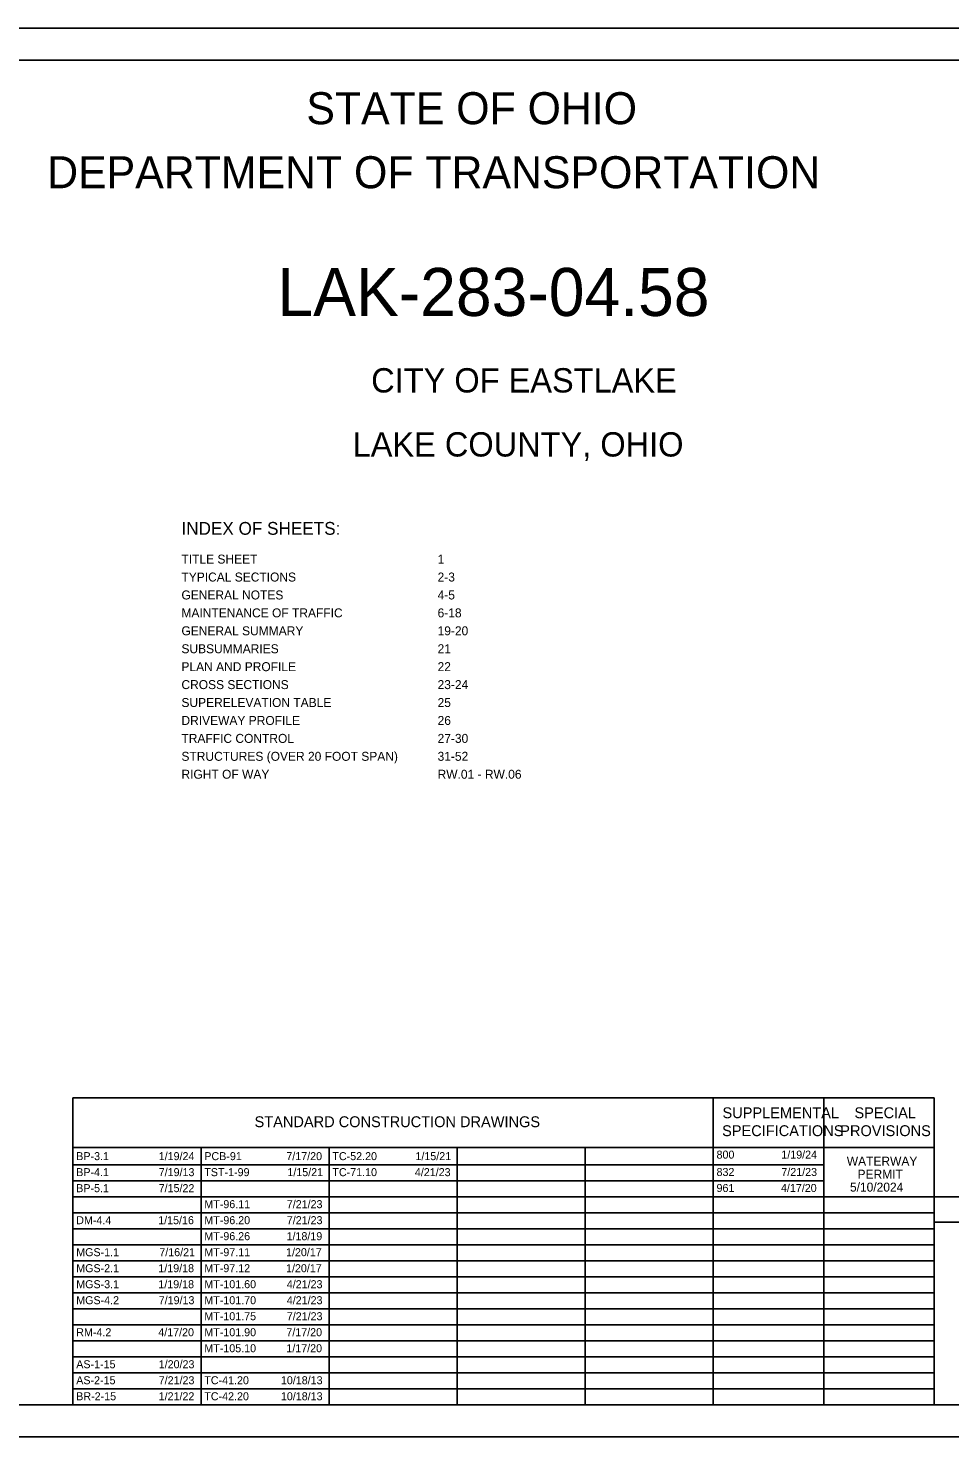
# Model space of a CAD drawing. Extents: x -5.4 to 71.3, y -12 to 22.
# Drawn here: x 9.45 to 23.84, y 0 to 22 of the extents above; entities that cross this region are included whole.
import ezdxf

# ---------------------------------------------------------------- set-up
doc = ezdxf.new("R2010")
doc.units = 0
for name, color, linetype in [('SH_Border', 7, 'Continuous'), ('SH_Cut_Line', 7, 'Continuous'), ('SH_Data', 7, 'Continuous'), ('SH_Text', 7, 'Continuous')]:
    doc.layers.add(name, color=color, linetype=linetype)

msp = doc.modelspace()

# ---------------------------------------------------------------- linework, layer by layer
at = {"layer": 'SH_Border'}
msp.add_lwpolyline([(1.5, 21.5), (33.5, 21.5), (33.5, 0.5), (1.5, 0.5)], close=True, dxfattribs=at)
at = {"layer": 'SH_Cut_Line'}
msp.add_lwpolyline([(0, 0), (34, 0), (34, 22), (0, 22)], close=True, dxfattribs=at)
at = {"layer": 'SH_Data'}
for p, q in [((10.15, 5.292), (23.6, 5.292)), ((10.15, 0.5), (10.15, 5.292)), ((20.15, 0.5), (20.15, 5.292)), ((21.875, 0.5), (21.875, 5.292)), ((23.6, 0.5), (23.6, 5.292)), ((10.15, 4.521), (23.6, 4.521)), ((12.15, 0.5), (12.15, 4.521)), ((14.15, 0.5), (14.15, 4.521)), ((16.15, 0.5), (16.15, 4.521)), ((18.15, 0.5), (18.15, 4.521)), ((10.15, 4.25), (21.875, 4.25)), ((10.15, 4), (21.875, 4)), ((10.15, 3.75), (23.6, 3.75)), ((23.6, 0.5), (23.6, 3.75)), ((23.6, 0.5), (23.6, 3.75)), ((23.6, 3.75), (26.4, 3.75)), ((10.15, 3.5), (23.6, 3.5)), ((23.6, 3.35), (26.4, 3.35)), ((10.15, 3.25), (23.6, 3.25)), ((10.15, 3), (23.6, 3)), ((10.15, 2.75), (23.6, 2.75)), ((10.15, 2.5), (23.6, 2.5)), ((10.15, 2.25), (23.6, 2.25)), ((10.15, 2), (23.6, 2)), ((10.15, 1.75), (23.6, 1.75)), ((10.15, 1.5), (23.6, 1.5)), ((10.15, 1.25), (23.6, 1.25)), ((10.15, 1), (23.6, 1)), ((10.15, 0.75), (23.6, 0.75)), ((23.6, 0.5), (26.4, 0.5)), ((23.6, 0.5), (26.4, 0.5))]:
    msp.add_line(p, q, dxfattribs=at)

# ---------------------------------------------------------------- texts
at = {"layer": 'SH_Text'}
for s, height, p in [('STATE OF OHIO', 0.5, (13.795, 20.5)), ('DEPARTMENT OF TRANSPORTATION', 0.5, (9.747, 19.5)), ('LAK-283-04.58', 0.75, (13.343, 17.505)), ('CITY OF EASTLAKE', 0.38, (14.807, 16.31)), ('LAKE COUNTY, OHIO', 0.38, (14.517, 15.31)), ('INDEX OF SHEETS:', 0.2, (11.844, 14.088)), ('TITLE SHEET', 0.14, (11.844, 13.638)), ('1', 0.14, (15.844, 13.638)), ('TYPICAL SECTIONS', 0.14, (11.844, 13.358)), ('2-3', 0.14, (15.844, 13.358)), ('GENERAL NOTES', 0.14, (11.844, 13.078)), ('4-5', 0.14, (15.844, 13.078)), ('MAINTENANCE OF TRAFFIC', 0.14, (11.844, 12.798)), ('6-18', 0.14, (15.844, 12.798)), ('GENERAL SUMMARY', 0.14, (11.844, 12.518)), ('19-20', 0.14, (15.844, 12.518)), ('SUBSUMMARIES', 0.14, (11.844, 12.238)), ('21', 0.14, (15.844, 12.238)), ('PLAN AND PROFILE', 0.14, (11.844, 11.958)), ('22', 0.14, (15.844, 11.958)), ('CROSS SECTIONS', 0.14, (11.844, 11.678)), ('23-24', 0.14, (15.844, 11.678)), ('SUPERELEVATION TABLE', 0.14, (11.844, 11.398)), ('25', 0.14, (15.844, 11.398)), ('DRIVEWAY PROFILE', 0.14, (11.844, 11.118)), ('26', 0.14, (15.844, 11.118)), ('TRAFFIC CONTROL', 0.14, (11.844, 10.838)), ('27-30', 0.14, (15.844, 10.838)), ('STRUCTURES (OVER 20 FOOT SPAN)', 0.14, (11.844, 10.558)), ('31-52', 0.14, (15.844, 10.558)), ('RIGHT OF WAY ', 0.14, (11.844, 10.278)), ('RW.01 - RW.06', 0.14, (15.844, 10.278)), ('SUPPLEMENTAL', 0.17, (20.293, 4.976)), ('SPECIAL', 0.17, (22.354, 4.976)), ('STANDARD CONSTRUCTION DRAWINGS', 0.17, (12.986, 4.836)), ('SPECIFICATIONS', 0.17, (20.287, 4.696)), ('PROVISIONS', 0.17, (22.132, 4.696)), ('BP-3.1', 0.125, (10.201, 4.321)), ('1/19/24', 0.125, (11.489, 4.321)), ('PCB-91', 0.125, (12.201, 4.321)), ('7/17/20', 0.125, (13.482, 4.321)), ('TC-52.20', 0.125, (14.201, 4.321)), ('1/15/21', 0.125, (15.498, 4.321)), ('800', 0.125, (20.2, 4.345)), ('1/19/24', 0.125, (21.212, 4.345)), ('BP-4.1', 0.125, (10.201, 4.071)), ('7/19/13', 0.125, (11.489, 4.071)), ('TST-1-99', 0.125, (12.201, 4.071)), ('1/15/21', 0.125, (13.498, 4.071)), ('TC-71.10', 0.125, (14.201, 4.071)), ('4/21/23', 0.125, (15.489, 4.071)), ('832', 0.125, (20.2, 4.074)), ('7/21/23', 0.125, (21.212, 4.074)), ('WATERWAY', 0.14, (22.234, 4.235)), ('5/10/2024', 0.14, (22.284, 3.83)), ('PERMIT', 0.14, (22.402, 4.032)), ('BP-5.1', 0.125, (10.201, 3.821)), ('7/15/22', 0.125, (11.488, 3.821)), ('961', 0.125, (20.2, 3.824)), ('4/17/20', 0.125, (21.206, 3.824)), ('MT-96.11', 0.125, (12.201, 3.571)), ('7/21/23', 0.125, (13.489, 3.571)), ('DM-4.4', 0.125, (10.201, 3.321)), ('1/15/16', 0.125, (11.481, 3.321)), ('MT-96.20', 0.125, (12.201, 3.321)), ('7/21/23', 0.125, (13.489, 3.321)), ('MT-96.26', 0.125, (12.201, 3.071)), ('1/18/19', 0.125, (13.485, 3.071)), ('MGS-1.1', 0.125, (10.201, 2.821)), ('7/16/21', 0.125, (11.498, 2.821)), ('MT-97.11', 0.125, (12.201, 2.821)), ('1/20/17', 0.125, (13.477, 2.821)), ('MGS-2.1', 0.125, (10.201, 2.571)), ('1/19/18', 0.125, (11.483, 2.571)), ('MT-97.12', 0.125, (12.201, 2.571)), ('1/20/17', 0.125, (13.477, 2.571)), ('MGS-3.1', 0.125, (10.201, 2.321)), ('1/19/18', 0.125, (11.483, 2.321)), ('MT-101.60', 0.125, (12.201, 2.321)), ('4/21/23', 0.125, (13.489, 2.321)), ('7/19/13', 0.125, (11.489, 2.071)), ('4/21/23', 0.125, (13.489, 2.071)), ('MGS-4.2', 0.125, (10.201, 2.071)), ('MT-101.70', 0.125, (12.201, 2.071)), ('MT-101.75', 0.125, (12.201, 1.821)), ('7/21/23', 0.125, (13.489, 1.821)), ('RM-4.2', 0.125, (10.201, 1.571)), ('4/17/20', 0.125, (11.482, 1.571)), ('MT-101.90', 0.125, (12.201, 1.571)), ('7/17/20', 0.125, (13.482, 1.571)), ('MT-105.10', 0.125, (12.201, 1.321)), ('1/17/20', 0.125, (13.482, 1.321)), ('AS-1-15', 0.125, (10.201, 1.071)), ('1/20/23', 0.125, (11.489, 1.071)), ('AS-2-15', 0.125, (10.201, 0.821)), ('7/21/23', 0.125, (11.489, 0.821)), ('TC-41.20', 0.125, (12.201, 0.821)), ('10/18/13', 0.125, (13.397, 0.821)), ('BR-2-15', 0.125, (10.201, 0.571)), ('1/21/22', 0.125, (11.488, 0.571)), ('TC-42.20', 0.125, (12.201, 0.571)), ('10/18/13', 0.125, (13.397, 0.571))]:
    msp.add_text(s, height=height, dxfattribs=at).set_placement(p)

doc.saveas('drawing.dxf')
